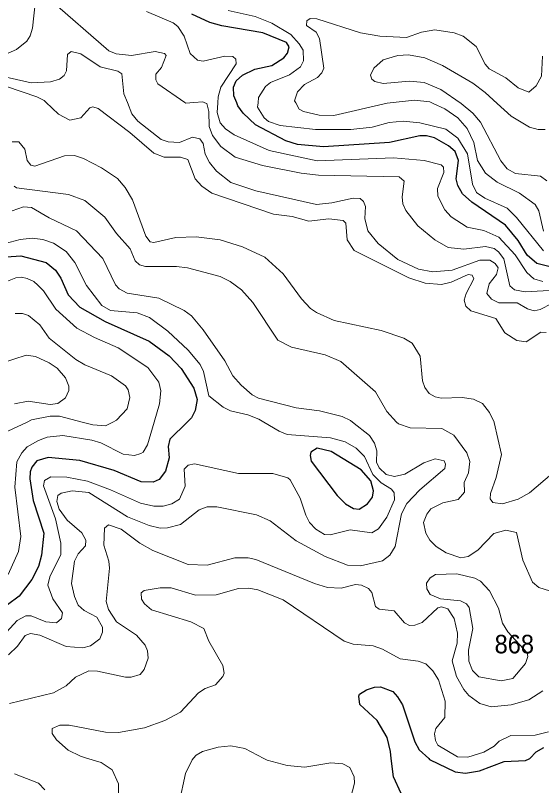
# Model space of a CAD drawing. Extents: x 473.9 to 500, y 7733.1 to 7760.8.
# Drawn here: x 487.667 to 489.935, y 7743.401 to 7746.72 of the extents above; entities that cross this region are included whole.
import ezdxf

# ---------------------------------------------------------------- set-up
doc = ezdxf.new("R2010")
doc.units = 0
doc.header["$LTSCALE"] = 0.032
doc.layers.add('1', color=7, linetype='Continuous', lineweight=25)
doc.layers.add('2', color=7, linetype='Continuous', lineweight=13)
doc.layers.add('21', color=7, linetype='Continuous')

msp = doc.modelspace()

# ---------------------------------------------------------------- linework, layer by layer
at = {"layer": '1'}
for points in [[(490.0241, 7745.6229), (489.9145, 7745.6506), (489.8731, 7745.6861), (489.8348, 7745.7492), (489.78, 7745.8159), (489.6352, 7745.9143), (489.5949, 7745.9502), (489.5737, 7745.9863), (489.5669, 7746.0157), (489.5777, 7746.0945), (489.5622, 7746.1328), (489.5342, 7746.1578), (489.4734, 7746.1924), (489.4391, 7746.2012), (489.4108, 7746.2012), (489.2796, 7746.1724), (488.9948, 7746.1539), (488.8829, 7746.1639), (488.8329, 7746.179), (488.7028, 7746.2476), (488.6484, 7746.2978), (488.6266, 7746.3301), (488.6213, 7746.3432), (488.6093, 7746.3727), (488.6076, 7746.411), (488.6196, 7746.4376), (488.6463, 7746.4627), (488.699, 7746.4884), (488.7725, 7746.5041), (488.8239, 7746.5367), (488.8401, 7746.5563), (488.8468, 7746.584), (488.8357, 7746.6024), (488.7334, 7746.6439), (488.5577, 7746.6746), (488.505, 7746.6889), (488.4277, 7746.725)], [(487.6287, 7745.6801), (487.6915, 7745.6838), (487.8001, 7745.6549), (487.8404, 7745.6215), (487.863, 7745.5878), (487.8944, 7745.5154), (487.9455, 7745.4629), (488.0539, 7745.4011), (488.2444, 7745.3155), (488.3299, 7745.2535), (488.3824, 7745.1978), (488.4367, 7745.1132)], [(488.4367, 7745.1132), (488.4514, 7745.0644), (488.4418, 7745.0178), (488.4258, 7744.9857), (488.4076, 7744.9675), (488.3336, 7744.8934), (488.3254, 7744.8628), (488.3305, 7744.8137), (488.3142, 7744.7562), (488.2875, 7744.7202), (488.2614, 7744.7082), (488.2099, 7744.7102), (488.0934, 7744.7595), (487.9449, 7744.8013), (487.8085, 7744.815), (487.7603, 7744.8005), (487.738, 7744.7738), (487.7304, 7744.7538), (487.7291, 7744.7226), (487.7439, 7744.6292), (487.7895, 7744.4889), (487.78, 7744.3948), (487.7668, 7744.346), (487.7387, 7744.2895), (487.6832, 7744.2174), (487.6338, 7744.1808)], [(489.3295, 7743.3674), (489.2972, 7743.4392), (489.2874, 7743.5178), (489.2836, 7743.5487), (489.2692, 7743.6091), (489.2266, 7743.6815), (489.1518, 7743.7515), (489.147, 7743.7871), (489.1508, 7743.7953), (489.1809, 7743.8143), (489.2149, 7743.8256), (489.2406, 7743.827), (489.2938, 7743.8066), (489.3148, 7743.7845), (489.3352, 7743.7487), (489.3891, 7743.5894), (489.4079, 7743.5557), (489.4491, 7743.5176), (489.4526, 7743.5143), (489.5625, 7743.4602), (489.6076, 7743.4556), (489.667, 7743.4645), (489.7735, 7743.5045), (489.8652, 7743.5101), (489.8818, 7743.5169), (489.8847, 7743.5181), (489.9125, 7743.5463), (489.9449, 7743.5655)]]:
    msp.add_lwpolyline(points, dxfattribs=at)
msp.add_lwpolyline([(489.2064, 7744.6435), (489.2104, 7744.671), (489.1999, 7744.7137), (489.1578, 7744.7612), (489.029, 7744.8402), (488.9673, 7744.8546), (488.9414, 7744.8382), (488.9372, 7744.8237), (488.9418, 7744.799), (489.0541, 7744.6517), (489.0903, 7744.6157), (489.124, 7744.5952), (489.1487, 7744.5926), (489.1856, 7744.6159)], close=True, dxfattribs=at)
at = {"layer": '2'}
for points in [[(487.6227, 7746.5517), (487.6717, 7746.5729), (487.7171, 7746.6093), (487.7313, 7746.6312), (487.7408, 7746.6644), (487.7543, 7746.7831)], [(487.8155, 7746.789), (488.0702, 7746.5663), (488.1021, 7746.5539), (488.1677, 7746.5471), (488.2696, 7746.5647), (488.3102, 7746.5561), (488.317, 7746.5463), (488.2965, 7746.4946), (488.2722, 7746.467), (488.2726, 7746.4416), (488.2812, 7746.425), (488.3972, 7746.3439), (488.4014, 7746.3409), (488.4363, 7746.3437), (488.4751, 7746.3469), (488.4841, 7746.3436), (488.4928, 7746.3404), (488.5015, 7746.3053), (488.5027, 7746.2404), (488.5169, 7746.2022), (488.5524, 7746.1542)], [(488.5847, 7746.7408), (488.7005, 7746.7148), (488.7728, 7746.6867), (488.854, 7746.6367), (488.8906, 7746.5976), (488.9073, 7746.5696), (488.9092, 7746.5234), (488.896, 7746.4981), (488.8481, 7746.4634), (488.7671, 7746.4309), (488.7455, 7746.4135), (488.7149, 7746.3663), (488.713, 7746.3429), (488.7115, 7746.3246), (488.7394, 7746.2776), (488.7589, 7746.2627), (488.8088, 7746.2449), (488.9606, 7746.2284), (489.1131, 7746.2275), (489.2045, 7746.2381), (489.2783, 7746.2582), (489.3385, 7746.264), (489.4103, 7746.2565), (489.5222, 7746.2299), (489.5749, 7746.19), (489.616, 7746.1236), (489.637, 7745.9924), (489.6552, 7745.9569), (489.6902, 7745.932), (489.7864, 7745.8893), (489.8267, 7745.8491), (489.9439, 7745.706)], [(489.4295, 7746.0944), (489.2971, 7746.1057), (488.968, 7746.0928), (488.7612, 7746.1378), (488.6098, 7746.2052), (488.5729, 7746.2306), (488.5502, 7746.2564), (488.5372, 7746.3015), (488.5394, 7746.3434), (488.5407, 7746.3691), (488.5527, 7746.4098), (488.6196, 7746.5108), (488.6173, 7746.5316), (488.604, 7746.5419), (488.5697, 7746.5436), (488.4764, 7746.5221), (488.4518, 7746.5273), (488.4205, 7746.5561), (488.3944, 7746.6306), (488.3675, 7746.6724), (488.3467, 7746.6882), (488.2331, 7746.736)], [(489.9388, 7746.5444), (489.9351, 7746.4575), (489.9123, 7746.4158), (489.8798, 7746.3896), (489.8348, 7746.4073), (489.7811, 7746.4509), (489.7089, 7746.4887), (489.6916, 7746.5099), (489.6535, 7746.586), (489.5967, 7746.6295), (489.5586, 7746.645), (489.4745, 7746.6571), (489.4172, 7746.6479), (489.3534, 7746.6248), (489.2385, 7746.6295), (489.1545, 7746.6449), (488.9664, 7746.7042), (488.9382, 7746.7065), (488.9239, 7746.6965), (488.9219, 7746.6762), (488.964, 7746.648), (488.9775, 7746.6204), (488.996, 7746.4925), (488.9877, 7746.4721), (488.9687, 7746.4522), (488.9139, 7746.4216), (488.8828, 7746.3903), (488.8705, 7746.3515), (488.8757, 7746.3424), (488.8906, 7746.3163), (488.9095, 7746.3051), (488.9764, 7746.2893), (489.0394, 7746.289), (489.2692, 7746.3411), (489.2703, 7746.3412), (489.388, 7746.3549), (489.4541, 7746.3468), (489.4674, 7746.3406), (489.5179, 7746.3173), (489.5743, 7746.2788), (489.6147, 7746.2317), (489.6425, 7746.1718), (489.6593, 7746.0939), (489.6936, 7746.0397), (489.7434, 7746.0009), (489.8402, 7745.9531), (489.9068, 7745.9055), (489.9234, 7745.8781), (489.9427, 7745.7904)], [(489.9793, 7745.478), (489.9294, 7745.4529), (489.9032, 7745.4473), (489.8739, 7745.4553), (489.8295, 7745.4814), (489.7506, 7745.4808), (489.7186, 7745.497), (489.6989, 7745.5216), (489.7096, 7745.5628), (489.7413, 7745.6033), (489.7476, 7745.6314), (489.7356, 7745.6512), (489.7116, 7745.6657), (489.6685, 7745.6647), (489.5491, 7745.6214), (489.4659, 7745.6151), (489.4054, 7745.6261), (489.3151, 7745.668), (489.2302, 7745.7362), (489.1868, 7745.7908), (489.1732, 7745.8441), (489.1765, 7745.8956), (489.168, 7745.918), (489.1537, 7745.9308), (489.1229, 7745.9319), (489.031, 7745.9123), (488.9647, 7745.9056), (488.7038, 7745.9639), (488.5959, 7745.9994), (488.5348, 7746.0481), (488.5033, 7746.0856), (488.4849, 7746.122), (488.4773, 7746.1676), (488.4627, 7746.188), (488.4311, 7746.1954), (488.3743, 7746.1724), (488.3258, 7746.1743), (488.295, 7746.1856), (488.1955, 7746.2644), (488.169, 7746.296), (488.1499, 7746.3446), (488.1354, 7746.3817), (488.1263, 7746.4684), (488.1084, 7746.4799), (488.0327, 7746.4978), (487.949, 7746.5542), (487.908, 7746.5638), (487.8914, 7746.5516), (487.8882, 7746.4813), (487.8782, 7746.4608), (487.858, 7746.4444), (487.8183, 7746.4335), (487.7356, 7746.429), (487.5315, 7746.4749)], [(489.9505, 7746.2285), (489.9199, 7746.2277), (489.8824, 7746.2387), (489.8041, 7746.2851), (489.7444, 7746.3398), (489.6925, 7746.3874), (489.6389, 7746.4279), (489.5077, 7746.5032), (489.4327, 7746.5367), (489.3615, 7746.5502), (489.3153, 7746.5468), (489.253, 7746.5285), (489.2122, 7746.4923), (489.1985, 7746.4623), (489.2037, 7746.4449), (489.217, 7746.4347), (489.2521, 7746.4257), (489.3658, 7746.4367), (489.4289, 7746.4303), (489.5008, 7746.4006), (489.5892, 7746.3403), (489.5892, 7746.3403), (489.6383, 7746.2985), (489.6721, 7746.2599), (489.7594, 7746.0925), (489.7869, 7746.059), (489.823, 7746.0386), (489.9302, 7746.0265), (489.9578, 7746.0063)], [(489.9553, 7745.3535), (489.9324, 7745.3556), (489.8685, 7745.3132), (489.8291, 7745.3193), (489.7763, 7745.3516), (489.7374, 7745.4133), (489.6297, 7745.4475), (489.6091, 7745.4669), (489.6022, 7745.4933), (489.6095, 7745.5211), (489.6429, 7745.5849), (489.636, 7745.6006), (489.6194, 7745.6037), (489.5457, 7745.5703), (489.504, 7745.5605), (489.4331, 7745.5657), (489.3628, 7745.5896), (489.1271, 7745.707), (489.0972, 7745.752), (489.091, 7745.8249), (489.0804, 7745.8364), (489.0182, 7745.8435), (488.9327, 7745.8334), (488.8606, 7745.8529), (488.7805, 7745.8628), (488.514, 7745.9534), (488.4709, 7745.9845), (488.4427, 7746.0158), (488.411, 7746.0983), (488.379, 7746.1095), (488.3091, 7746.1084), (488.2642, 7746.1265), (488.1609, 7746.2146), (488.0235, 7746.3183), (488.0009, 7746.325), (487.9889, 7746.3215), (487.9493, 7746.2785), (487.9027, 7746.2683), (487.8526, 7746.2946), (487.7987, 7746.3457), (487.7916, 7746.3524), (487.7604, 7746.3689), (487.4923, 7746.4593)], [(487.6535, 7746.1756), (487.6822, 7746.1752), (487.7088, 7746.1428), (487.7182, 7746.0942), (487.7344, 7746.0737), (487.7517, 7746.0705), (487.8792, 7746.1139), (487.9215, 7746.1155), (487.9608, 7746.1036), (488.0391, 7746.0629), (488.1071, 7746.0167), (488.14, 7745.9782), (488.1717, 7745.9247), (488.2294, 7745.7678), (488.2481, 7745.7438), (488.2645, 7745.7407), (488.3591, 7745.763), (488.4459, 7745.7663), (488.5499, 7745.7532), (488.6459, 7745.7226), (488.7418, 7745.6778), (488.8209, 7745.6068), (488.9002, 7745.4981), (488.9396, 7745.4568), (488.9653, 7745.4391), (489.0414, 7745.4049), (489.2441, 7745.3624)], [(488.5524, 7746.1542), (488.6143, 7746.1094), (488.7323, 7746.0725), (488.8988, 7746.0395), (488.9734, 7746.0317), (489.321, 7746.0242), (489.3432, 7746.0049), (489.3344, 7745.9381), (489.3376, 7745.9072), (489.3497, 7745.8796), (489.4022, 7745.8133), (489.4757, 7745.7533), (489.5319, 7745.7201), (489.6, 7745.7118), (489.6937, 7745.7244), (489.7302, 7745.715), (489.7488, 7745.7015), (489.7729, 7745.6703), (489.7989, 7745.5549), (489.8189, 7745.5366), (489.8642, 7745.5284), (489.9944, 7745.5355)], [(489.9409, 7745.5735), (489.9022, 7745.5844), (489.871, 7745.6124), (489.8209, 7745.6876), (489.7516, 7745.7638), (489.6868, 7745.7922), (489.614, 7745.8079), (489.5451, 7745.8516), (489.5186, 7745.8815), (489.4875, 7745.9412), (489.4864, 7745.9745), (489.5137, 7746.0426), (489.5127, 7746.0651), (489.5024, 7746.0757), (489.4295, 7746.0944)], [(487.6627, 7745.9845), (487.6719, 7745.9769)], [(487.6719, 7745.9769), (487.8965, 7745.9487), (487.9672, 7745.9227), (488.053, 7745.8502), (488.1034, 7745.7795), (488.1622, 7745.7133), (488.1842, 7745.6622), (488.2022, 7745.6454), (488.2284, 7745.6385), (488.3613, 7745.6384), (488.4095, 7745.6327), (488.5499, 7745.5944), (488.5933, 7745.5728), (488.6412, 7745.5372), (488.6904, 7745.4825), (488.7981, 7745.321), (488.857, 7745.29), (489.0029, 7745.2571), (489.0703, 7745.2289), (489.2193, 7745.0981), (489.2689, 7745.0125), (489.3103, 7744.9675), (489.3178, 7744.9594), (489.3694, 7744.9431), (489.5046, 7744.9403), (489.5569, 7744.9116), (489.6125, 7744.8344), (489.6265, 7744.7981), (489.6197, 7744.7482), (489.6009, 7744.7073), (489.6027, 7744.6658), (489.5758, 7744.634), (489.5099, 7744.6201), (489.4581, 7744.5942), (489.4399, 7744.5713), (489.4261, 7744.5348), (489.4366, 7744.4888), (489.4534, 7744.4589), (489.4807, 7744.4319), (489.5239, 7744.404), (489.5869, 7744.3823), (489.6187, 7744.3877), (489.6598, 7744.4154), (489.7299, 7744.4872), (489.7807, 7744.5023), (489.8267, 7744.4917), (489.8549, 7744.3724), (489.8962, 7744.2779), (489.923, 7744.255), (489.9687, 7744.2403)], [(489.225, 7744.8441), (489.2156, 7744.8773), (489.1932, 7744.9096), (489.1199, 7744.9675), (489.111, 7744.9745), (489.0753, 7744.991), (488.9774, 7745.0164), (488.8772, 7745.0289), (488.7156, 7745.0703), (488.688, 7745.0854), (488.6401, 7745.1266), (488.6044, 7745.1673), (488.5702, 7745.2321), (488.476, 7745.3647), (488.4258, 7745.4246), (488.3947, 7745.4482), (488.2857, 7745.5013), (488.149, 7745.5225), (488.1141, 7745.5417), (488.0988, 7745.559), (488.0449, 7745.672), (487.9305, 7745.7912), (487.8124, 7745.8476), (487.7363, 7745.8914), (487.703, 7745.8949), (487.6542, 7745.8772)], [(487.6237, 7745.7368), (487.6878, 7745.7545), (487.7391, 7745.7598), (487.785, 7745.7542), (487.8317, 7745.738), (487.8858, 7745.7023), (487.9229, 7745.655), (487.9741, 7745.5566), (488.0396, 7745.4693), (488.0777, 7745.448), (488.1924, 7745.4383), (488.246, 7745.4176), (488.3244, 7745.3594), (488.4125, 7745.2771), (488.4636, 7745.2155), (488.4785, 7745.1855), (488.501, 7745.0806), (488.5624, 7745.0321), (488.5939, 7745.0163), (488.6694, 7744.9984), (488.7166, 7744.9804), (488.7381, 7744.9675), (488.8039, 7744.928), (488.8384, 7744.9143), (489.0254, 7744.9002), (489.089, 7744.8819), (489.1358, 7744.8556), (489.1716, 7744.8188), (489.2086, 7744.7417), (489.2439, 7744.7054), (489.2885, 7744.6781), (489.2998, 7744.6632), (489.3011, 7744.6329), (489.2681, 7744.5573), (489.233, 7744.5081), (489.204, 7744.49), (489.1095, 7744.503), (489.0246, 7744.4815), (488.9997, 7744.4831), (488.9617, 7744.5061), (488.9356, 7744.5354), (488.9188, 7744.566), (488.894, 7744.6394), (488.8523, 7744.7193), (488.8416, 7744.7275), (488.7771, 7744.7462), (488.6288, 7744.7459), (488.439, 7744.7878), (488.412, 7744.7821), (488.3944, 7744.7641), (488.3985, 7744.6919), (488.375, 7744.636), (488.3419, 7744.6152), (488.3039, 7744.6055), (488.2637, 7744.6055), (488.2063, 7744.6182), (488.0777, 7744.6761), (487.978, 7744.713), (487.889, 7744.7308), (487.82, 7744.731), (487.7931, 7744.7155), (487.7883, 7744.6935), (487.8405, 7744.5514), (487.863, 7744.4453), (487.8628, 7744.3965), (487.8156, 7744.3006), (487.8076, 7744.2647), (487.8285, 7744.2057), (487.8708, 7744.1457), (487.866, 7744.1214), (487.8443, 7744.1032), (487.798, 7744.1065), (487.7351, 7744.1332), (487.7121, 7744.1331), (487.6757, 7744.1132), (487.6288, 7744.0621)], [(487.6363, 7744.3111), (487.6806, 7744.41), (487.6902, 7744.4743), (487.6645, 7744.6866), (487.6733, 7744.7959), (487.695, 7744.8345), (487.7183, 7744.8602), (487.7666, 7744.8884), (487.8044, 7744.9028), (487.8719, 7744.9093), (487.9973, 7744.89), (488.0359, 7744.8779), (488.1324, 7744.8289), (488.1807, 7744.8232), (488.208, 7744.8321), (488.2184, 7744.8385), (488.2361, 7744.8699), (488.2654, 7744.9675), (488.2892, 7745.0468), (488.2948, 7745.1015), (488.286, 7745.14), (488.2385, 7745.2028), (488.1099, 7745.288), (488.0086, 7745.3314), (487.9322, 7745.3724), (487.8414, 7745.4536), (487.7883, 7745.5324), (487.7642, 7745.5573), (487.7473, 7745.5726), (487.7176, 7745.5863), (487.6934, 7745.5919), (487.6693, 7745.5895), (487.6122, 7745.5654)], [(487.6671, 7745.4348), (487.6977, 7745.4358), (487.7244, 7745.4267), (487.7729, 7745.3868), (487.8132, 7745.329), (487.9272, 7745.2371), (487.9673, 7745.2136), (488.081, 7745.1665), (488.142, 7745.1237), (488.1532, 7745.1058), (488.1605, 7745.073), (488.1492, 7745.0242), (488.1026, 7744.9752), (488.0879, 7744.9675), (488.0562, 7744.9509), (488.0011, 7744.9557), (487.9552, 7744.9675), (487.8569, 7744.9928), (487.8171, 7744.9928), (487.7368, 7744.9767), (487.7175, 7744.9675), (487.6355, 7744.9284)], [(489.2441, 7745.3624), (489.3411, 7745.3292), (489.3776, 7745.308), (489.4117, 7745.252), (489.4222, 7745.1453), (489.4319, 7745.1169), (489.4509, 7745.091), (489.4764, 7745.0764), (489.502, 7745.0707), (489.593, 7745.0732), (489.6413, 7745.0666), (489.6808, 7745.0479), (489.7109, 7745.0092), (489.7301, 7744.9675), (489.7307, 7744.9663), (489.762, 7744.8282), (489.7395, 7744.7283), (489.7154, 7744.6602), (489.7141, 7744.6374), (489.7246, 7744.6205), (489.7672, 7744.6147), (489.8342, 7744.6361), (489.883, 7744.6631), (489.9796, 7744.7439)], [(487.6634, 7745.0461), (487.7218, 7745.0572), (487.8178, 7745.0427), (487.8506, 7745.0478), (487.8835, 7745.0713), (487.8971, 7745.103), (487.8979, 7745.1222), (487.8828, 7745.1586), (487.8478, 7745.1994), (487.8126, 7745.223), (487.7539, 7745.2495), (487.7142, 7745.2565), (487.6078, 7745.2208)], [(487.6382, 7743.9654), (487.6761, 7744.0021), (487.7099, 7744.0474), (487.732, 7744.0569), (487.7732, 7744.0491), (487.8869, 7744.0006), (487.9587, 7743.9943), (487.9913, 7744.0034), (488.0308, 7744.033), (488.0435, 7744.0626), (488.0424, 7744.0834), (488.0178, 7744.1273), (487.9638, 7744.1554), (487.9379, 7744.1793), (487.9226, 7744.2154), (487.9097, 7744.2716), (487.9228, 7744.3686), (487.9378, 7744.4002), (487.9702, 7744.4343), (487.9714, 7744.4582), (487.9542, 7744.4908), (487.8906, 7744.5456), (487.8555, 7744.5923), (487.8463, 7744.6249), (487.8507, 7744.651), (487.8644, 7744.6612), (487.9115, 7744.6711), (487.9844, 7744.6648), (488.1499, 7744.5594), (488.2444, 7744.5221), (488.2915, 7744.5105), (488.3227, 7744.5119), (488.3795, 7744.5263), (488.4597, 7744.5892), (488.4941, 7744.6026), (488.5354, 7744.602), (488.7059, 7744.5685), (488.7659, 7744.5425), (488.878, 7744.4561), (489.0028, 7744.3879), (489.0994, 7744.3504), (489.155, 7744.3481), (489.2489, 7744.3702), (489.2814, 7744.3946), (489.3035, 7744.4308), (489.3312, 7744.5723), (489.355, 7744.6168), (489.4111, 7744.6756), (489.518, 7744.7682), (489.5208, 7744.7857), (489.5156, 7744.8), (489.4766, 7744.8095), (489.4279, 7744.7923), (489.3459, 7744.7437), (489.3009, 7744.7332), (489.2647, 7744.7419), (489.2355, 7744.7701), (489.2237, 7744.7953), (489.225, 7744.8441)], [(489.0709, 7744.2516), (489.0125, 7744.255), (488.9562, 7744.2721), (488.7042, 7744.3754), (488.671, 7744.3825), (488.6131, 7744.3826), (488.4941, 7744.3513), (488.4127, 7744.3539), (488.2601, 7744.4144), (488.2038, 7744.446), (488.1238, 7744.5066), (488.0683, 7744.5246), (488.0518, 7744.5102), (488.0485, 7744.4377), (488.0702, 7744.3686), (488.0727, 7744.3375), (488.0592, 7744.1952), (488.0689, 7744.1607), (488.1036, 7744.1071), (488.189, 7744.0501), (488.2264, 7744.0063), (488.2361, 7743.9817), (488.2392, 7743.95), (488.223, 7743.9013), (488.2053, 7743.8796), (488.1667, 7743.869), (488.142, 7743.8689), (488.022, 7743.8944), (487.9836, 7743.8963), (487.9266, 7743.8687), (487.8859, 7743.8307), (487.8314, 7743.8011), (487.6425, 7743.7556)], [(489.9643, 7743.6331), (489.9071, 7743.6181), (489.8032, 7743.6171), (489.7522, 7743.5922), (489.7303, 7743.5711), (489.6863, 7743.5452), (489.617, 7743.5237), (489.5722, 7743.5249), (489.4881, 7743.5755), (489.4775, 7743.5951), (489.4735, 7743.6247), (489.4788, 7743.6472), (489.5187, 7743.6953), (489.5193, 7743.7645), (489.4904, 7743.8567), (489.4658, 7743.8957), (489.4365, 7743.9259), (489.4027, 7743.937), (489.326, 7743.9475), (489.2494, 7743.9889), (489.2097, 7744.0031), (489.123, 7744.0111), (489.0837, 7744.0237), (488.8219, 7744.2022), (488.7128, 7744.2451), (488.6732, 7744.2515), (488.6294, 7744.2501), (488.5322, 7744.2236), (488.4433, 7744.2224), (488.3382, 7744.2531), (488.2915, 7744.2531), (488.2224, 7744.2425), (488.2096, 7744.2324), (488.211, 7744.2041), (488.2235, 7744.1841), (488.2543, 7744.158), (488.4229, 7744.107), (488.4801, 7744.0778), (488.501, 7744.0241), (488.5619, 7743.9194)], [(489.9405, 7743.81), (489.8799, 7743.7709), (489.8043, 7743.7499), (489.7173, 7743.7403), (489.6692, 7743.7547), (489.6223, 7743.79), (489.6004, 7743.8152), (489.5688, 7743.8718), (489.5499, 7743.9382), (489.5715, 7744.0148), (489.5732, 7744.0588), (489.5587, 7744.1216), (489.5311, 7744.1624), (489.504, 7744.171), (489.4879, 7744.1678), (489.4208, 7744.1042), (489.3893, 7744.0922), (489.3652, 7744.0909), (489.3439, 7744.102), (489.2993, 7744.1548), (489.2354, 7744.1615), (489.2191, 7744.1732), (489.2038, 7744.2335), (489.1887, 7744.2508), (489.1593, 7744.2655), (489.1336, 7744.2675), (489.0709, 7744.2516)], [(488.5619, 7743.9194), (488.5666, 7743.8854), (488.5617, 7743.8713), (488.5296, 7743.8358), (488.4847, 7743.8196), (488.456, 7743.8008), (488.3784, 7743.7176), (488.3114, 7743.6817), (488.2238, 7743.6506), (488.1125, 7743.6301), (488.0551, 7743.6309), (487.8993, 7743.6613), (487.859, 7743.6613), (487.8259, 7743.648), (487.8264, 7743.6264), (487.8441, 7743.599), (487.8942, 7743.5538), (487.9479, 7743.5278), (487.974, 7743.5198), (488.0375, 7743.5005), (488.0841, 7743.4692), (488.1121, 7743.4086), (488.1123, 7743.3588)], [(488.3726, 7743.3277), (488.4002, 7743.4537), (488.429, 7743.5119), (488.4353, 7743.5191), (488.4466, 7743.532), (488.4743, 7743.5476), (488.5408, 7743.5665), (488.5957, 7743.5722), (488.656, 7743.5609), (488.7383, 7743.5187), (488.7531, 7743.5111), (488.8394, 7743.4884), (488.9149, 7743.4813), (489.0275, 7743.4989), (489.079, 7743.4958), (489.1089, 7743.4793), (489.1269, 7743.4386), (489.1293, 7743.4114), (489.0775, 7743.2134)], [(487.6635, 7743.4521), (487.7669, 7743.4116), (487.794, 7743.3834)]]:
    msp.add_lwpolyline(points, dxfattribs=at)
msp.add_lwpolyline([(489.6653, 7743.8694), (489.7613, 7743.853), (489.8113, 7743.8624), (489.8664, 7743.9279), (489.8762, 7743.9569), (489.8733, 7743.9733), (489.7897, 7744.0635), (489.767, 7744.1013), (489.7498, 7744.166), (489.7103, 7744.2412), (489.6716, 7744.2825), (489.6471, 7744.2956), (489.5704, 7744.3141), (489.4783, 7744.3109), (489.4544, 7744.296), (489.4398, 7744.2737), (489.44, 7744.249), (489.4553, 7744.2242), (489.4988, 7744.2055), (489.586, 7744.1976), (489.6116, 7744.1842), (489.6229, 7744.1687), (489.6389, 7744.0777), (489.6199, 7743.9851), (489.6211, 7743.9374), (489.6371, 7743.8967)], close=True, dxfattribs=at)

# ---------------------------------------------------------------- texts
at = {"layer": '21', "width": 0.95}
msp.add_text('868', height=0.08, dxfattribs=at).set_placement((489.7327, 7743.971))

doc.saveas('drawing.dxf')
